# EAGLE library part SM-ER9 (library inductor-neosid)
TRANSFORMER SMD converter and transformer acc. to customer specification
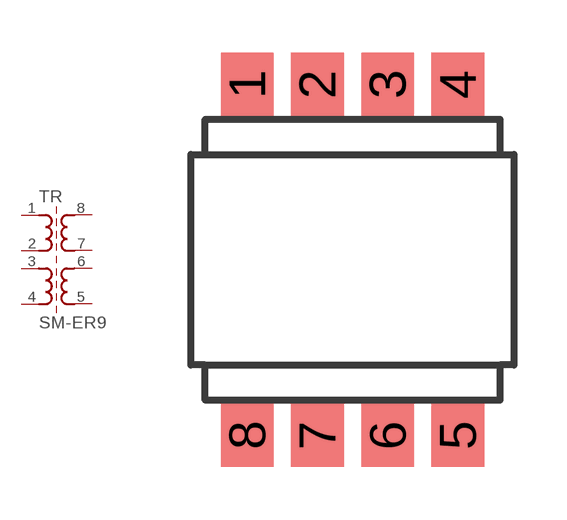
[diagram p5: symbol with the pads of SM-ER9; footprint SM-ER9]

Designator prefix TR

## SM-ER9 (OC_FARNELL: unknown; OC_NEWARK: unknown)  [SM-ER9]
1  1  pas
2  2  pas
3  3  pas
4  4  pas
5  5  pas
6  6  pas
7  7  pas
8  8  pas

## Footprint SM-ER9 (pad centres in mm)
SMD CONVERTER/TRANSFORMER acc. to customer specification, 9.5 x 11.6 x 5.5 mm
smd 1.5 x 1.8: 1 -3,5; 2 -1,5; 3 1,5; 4 3,5; 5 3,-5; 6 1,-5; 7 -1,-5; 8 -3,-5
